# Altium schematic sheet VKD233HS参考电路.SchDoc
size A4
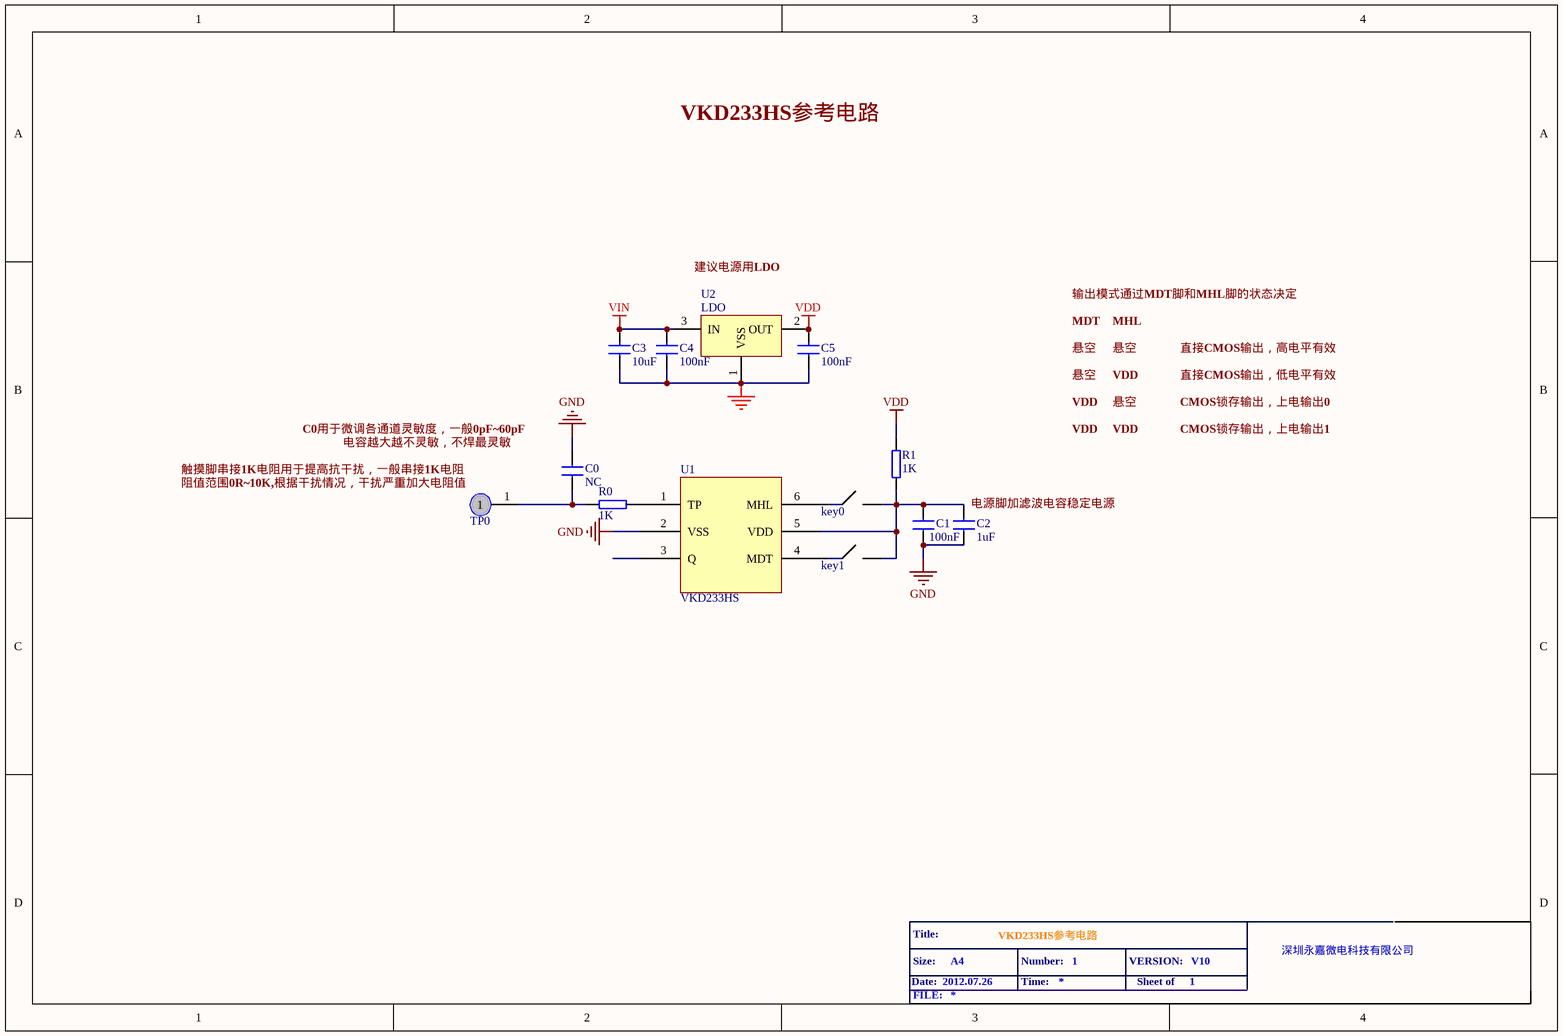
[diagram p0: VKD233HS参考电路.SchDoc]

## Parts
C0  value NC  [0603-C]  (hidden comment: 10uF)
C1  100nF  [0603-C]
C2  value 1uF  [0603-C]  (hidden comment: 10uF)
C3  10uF  [0805-C]
C4  100nF  [0805-C]
C5  100nF  [0805-C]
key0  单刀单掷开关  (value not drawn)
key1  单刀单掷开关  (value not drawn)
R0  1K  [0603-R]
R1  1K  [0603-R]
TP0  TPAD  [TP-PAD0]  (value not drawn)
U1  VKD233HS
U2  LDO  [SOT-23]

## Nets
GND: C0.1 C1.2 C2.2 C3.2 C4.2 C5.2 U1.2(VSS) U2.1(VSS)
VDD: C5.1 R1.1 U2.2(OUT)
VIN: C3.1 C4.1 U2.3(IN)
NetC0_2: C0.2 R0.2 TP0.1
NetC1_1: C1.1 C2.1 R1.2 U1.5(VDD)
NetR0_1: R0.1 U1.1(TP)

Not connected (* = marked no-connect by the designer): U1 3(Q) 4(MDT) 6(MHL)

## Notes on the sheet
- VKD233HS参考电路
- 建议电源用LDO
- 输出模式通过MDT脚和MHL脚的状态决定
- MDT
- 悬空
- MHL
- VDD
- 直接CMOS输出，高电平有效
- 直接CMOS输出，低电平有效
- C0用于微调各通道灵敏度，一般0pF~60pF
- 电容越大越不灵敏，不焊最灵敏
- CMOS锁存输出，上电输出0
- CMOS锁存输出，上电输出1
- 触摸脚串接1K电阻用于提高抗干扰，一般串接1K电阻
- 阻值范围0R
  0K,根据干扰情况，干扰严重加大电阻值
- (near C2) 电源脚加滤波电容稳定电源
- Date:
- Title:
- Size:
- 2012.07.26
- A4
- Number:
- Time:
- 1
- VERSION:
- Sheet of
- V10
- 深圳永嘉微电科技有限公司
- FILE:

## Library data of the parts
C0-C5 = CAP: Capacitor
R0 R1 = RES: Resistor
TP0 = TPAD: TESTING
U1 = VKD233HS DFN6L
U2 = V6206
